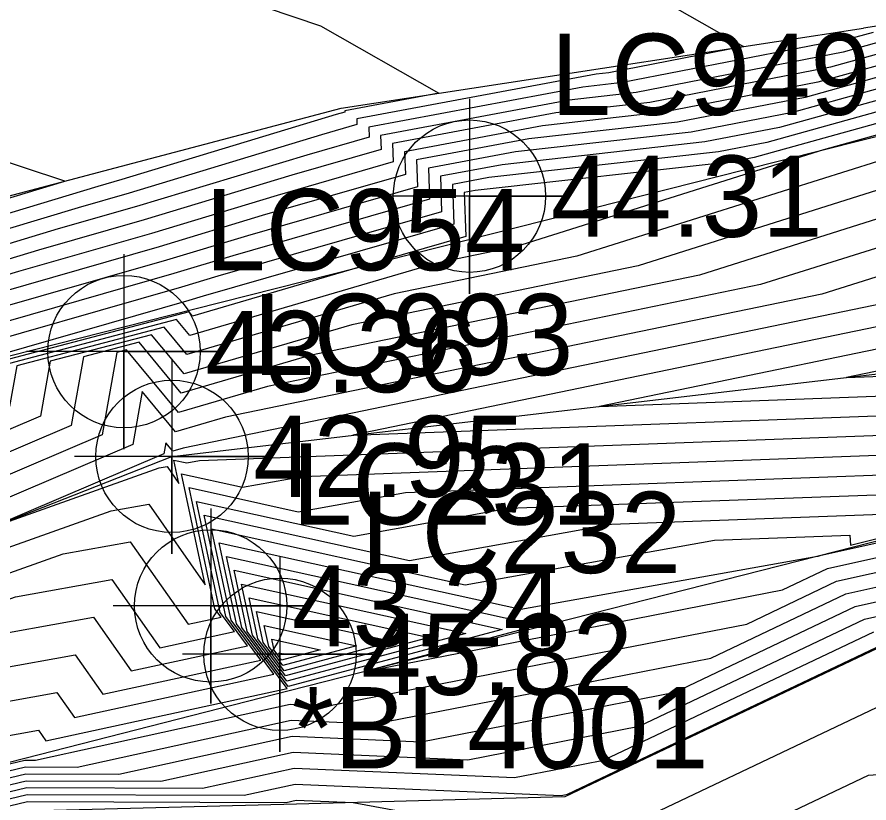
# Model space of a CAD drawing. Extents: x 2188792 to 2191981, y 386090 to 389710.
# Drawn here: x 2190212.42 to 2190238.64, y 387929.77 to 387953.95 of the extents above; entities that cross this region are included whole.
import ezdxf

# ---------------------------------------------------------------- set-up
doc = ezdxf.new("R2010")
doc.units = 0
for name, color, linetype in [('DTM Contours Major', 7, 'Continuous'), ('DTM Contours Minor', 7, 'Continuous'), ('Exist DTM Breakline Underwater', 7, 'Continuous'), ('Exist DTM Breakline Underwater Cogo Elevation', 7, 'Continuous'), ('Exist DTM Breakline Underwater Cogo Number', 7, 'Continuous'), ('Exist DTM Breakline Underwater Cogo Point CELL', 7, 'Continuous'), ('Exist DTM Regular Point Underwater CELL', 7, 'Continuous'), ('Exist DTM Regular Point Underwater Cogo Comment', 7, 'Continuous'), ('Exist DTM Regular Point Underwater Cogo Elevation', 7, 'Continuous'), ('Exist DTM Regular Point Underwater Cogo Number', 7, 'Continuous'), ('PH Exist DTM Breakline', 7, 'Continuous')]:
    doc.layers.add(name, color=color, linetype=linetype)

msp = doc.modelspace()

# ---------------------------------------------------------------- linework, layer by layer
at = {"layer": 'DTM Contours Major'}
for points in [[(2190238.761, 387953.476), (2190238.236, 387953.33), (2190231.049, 387951.931), (2190229.826, 387951.794), (2190223.241, 387950.56), (2190223.252, 387950.255), (2190221.331, 387949.704), (2190216.099, 387948.12), (2190213.685, 387947.428), (2190208.783, 387945.95), (2190204.376, 387944.62), (2190201.304, 387943.745), (2190197.863, 387942.764), (2190191.097, 387939.659), (2190187.751, 387938.056), (2190186.22, 387937.225), (2190179.234, 387934.025), (2190177.951, 387933.325)], [(2190241.141, 387952.366), (2190236.279, 387951.015), (2190233.163, 387950.409), (2190227.76, 387949.804), (2190225.079, 387949.301), (2190225.113, 387948.341), (2190219.055, 387946.601), (2190217.247, 387946.054), (2190210.637, 387944.16), (2190209.214, 387943.73), (2190207.934, 387943.344), (2190201.011, 387941.371), (2190193.254, 387939.16), (2190192.262, 387938.705), (2190191.772, 387938.47), (2190185.14, 387934.868), (2190184.293, 387934.48), (2190177.559, 387930.807)], [(2190243.465, 387950.942), (2190236.16, 387948.641), (2190229.647, 387946.589), (2190224.024, 387945.428), (2190217.646, 387943.561), (2190216.945, 387944.409), (2190212.415, 387943.221), (2190212.19, 387941.963), (2190203.611, 387938.301), (2190198.377, 387936.644), (2190193.887, 387935.221), (2190192.821, 387934.763), (2190189.103, 387932.693), (2190185.528, 387930.702), (2190172.055, 387924.838)], [(2190239.074, 387945.134), (2190217.532, 387940.686), (2190217.208, 387940.591), (2190216.993, 387940.852), (2190216.931, 387940.51), (2190211.569, 387938.221), (2190216.791, 387940.078), (2190217.034, 387940.122), (2190217.401, 387939.598), (2190217.247, 387940.318), (2190217.643, 387940.231), (2190218.033, 387940.301), (2190242.904, 387941.223)], [(2190174.772, 387918.95), (2190187.655, 387925.086), (2190191.189, 387926.924), (2190194.861, 387928.834), (2190195.881, 387929.317), (2190200.477, 387930.285), (2190209.419, 387933.465), (2190214.208, 387934.324), (2190215.059, 387933.111), (2190219.916, 387934.166), (2190219.005, 387935.394), (2190218.404, 387938.199), (2190226.213, 387936.479), (2190233.879, 387937.854), (2190238.048, 387938.009), (2190238.066, 387937.699), (2190244.835, 387939.381)], [(2190175.323, 387915.538), (2190181.724, 387918.921), (2190182.593, 387919.342), (2190188.861, 387922.648), (2190189.628, 387923.046), (2190195.733, 387926.265), (2190196.621, 387926.724), (2190203.158, 387928.251), (2190204.711, 387928.684), (2190206.464, 387929.173), (2190212.686, 387930.663), (2190215.555, 387930.653), (2190220.883, 387931.821), (2190224.858, 387931.651), (2190229.111, 387932.482), (2190232.668, 387933.178), (2190238.216, 387935.813), (2190241.557, 387936.557)], [(2190219.56, 387936.08), (2190225.106, 387934.858), (2190220.677, 387933.675), (2190219.831, 387934.816), (2190219.56, 387936.08)], [(2190174.341, 387884.909), (2190179.78, 387876.537), (2190184.682, 387879.952), (2190189.719, 387877.326), (2190192.093, 387885.619), (2190199.916, 387886.43), (2190200.828, 387887.573), (2190201.355, 387888.233), (2190200.535, 387890.18), (2190200.972, 387898.729), (2190211.107, 387898.557), (2190228.203, 387913.529), (2190222.305, 387928.372), (2190230.642, 387926.831), (2190238.626, 387930.623), (2190241.69, 387930.853)]]:
    msp.add_lwpolyline(points, dxfattribs=at)
at = {"layer": 'DTM Contours Minor'}
for points in [[(2190208.525, 387947.281), (2190213.89, 387948.9), (2190208.847, 387950.558), (2190207.29, 387949.272), (2190201.069, 387949.623), (2190198.133, 387949.956), (2190190.044, 387946.776), (2190181.258, 387951.986), (2190179.765, 387960.073)], [(2190227.6, 387957.129), (2190234.774, 387953.043), (2190230.626, 387952.236), (2190230.239, 387952.193), (2190222.873, 387950.812), (2190222.879, 387950.638), (2190221.786, 387950.324), (2190215.869, 387948.533), (2190214.294, 387948.082), (2190208.697, 387946.394), (2190203.664, 387944.875), (2190201.363, 387944.219), (2190198.785, 387943.484), (2190190.864, 387939.85), (2190186.947, 387937.973), (2190186.437, 387937.696), (2190178.222, 387933.934)], [(2190216.682, 387955.398), (2190221.76, 387953.676), (2190225.395, 387951.605), (2190222.506, 387951.063), (2190222.507, 387951.021), (2190222.242, 387950.945), (2190215.639, 387948.946), (2190214.904, 387948.736), (2190208.611, 387946.838), (2190202.953, 387945.131), (2190201.422, 387944.694), (2190199.706, 387944.205), (2190190.631, 387940.041), (2190187.233, 387938.413), (2190184.778, 387941.158), (2190178.644, 387939.932), (2190174.81, 387940.464)], [(2190239.713, 387953.032), (2190237.453, 387952.404), (2190231.894, 387951.323), (2190228.999, 387950.998), (2190223.976, 387950.056), (2190223.996, 387949.49), (2190220.421, 387948.463), (2190216.558, 387947.293), (2190212.465, 387946.121), (2190208.955, 387945.062), (2190205.799, 387944.11), (2190201.187, 387942.795), (2190196.019, 387941.322), (2190191.563, 387939.277), (2190189.359, 387938.222), (2190185.788, 387936.282), (2190181.257, 387934.207), (2190177.794, 387932.318)], [(2190239.237, 387953.254), (2190237.845, 387952.867), (2190231.472, 387951.627), (2190229.413, 387951.396), (2190223.608, 387950.308), (2190223.624, 387949.873), (2190220.876, 387949.083), (2190216.328, 387947.707), (2190213.075, 387946.775), (2190208.869, 387945.506), (2190205.087, 387944.365), (2190201.246, 387943.27), (2190196.941, 387942.043), (2190191.33, 387939.468), (2190188.555, 387938.139), (2190186.004, 387936.753), (2190180.245, 387934.116), (2190177.873, 387932.822)], [(2190240.189, 387952.81), (2190237.062, 387951.941), (2190232.317, 387951.018), (2190228.586, 387950.6), (2190224.344, 387949.805), (2190224.368, 387949.107), (2190219.965, 387947.842), (2190216.788, 387946.88), (2190211.856, 387945.467), (2190209.041, 387944.618), (2190206.51, 387943.855), (2190201.128, 387942.32), (2190195.097, 387940.601), (2190191.796, 387939.086), (2190190.164, 387938.304), (2190185.572, 387935.811), (2190182.269, 387934.298), (2190177.716, 387931.814)], [(2190240.665, 387952.588), (2190236.67, 387951.478), (2190232.74, 387950.714), (2190228.173, 387950.202), (2190224.711, 387949.553), (2190224.741, 387948.724), (2190219.51, 387947.221), (2190217.017, 387946.467), (2190211.246, 387944.813), (2190209.128, 387944.174), (2190207.222, 387943.599), (2190201.07, 387941.846), (2190194.175, 387939.88), (2190192.029, 387938.896), (2190190.968, 387938.387), (2190185.356, 387935.339), (2190183.281, 387934.389), (2190177.638, 387931.31)], [(2190241.616, 387952.144), (2190235.887, 387950.552), (2190233.585, 387950.105), (2190227.346, 387949.406), (2190225.447, 387949.05), (2190225.485, 387947.958), (2190218.6, 387945.98), (2190217.477, 387945.64), (2190210.027, 387943.506), (2190209.3, 387943.286), (2190208.645, 387943.089), (2190200.952, 387940.896), (2190194.479, 387939.051), (2190192.511, 387938.427), (2190192.475, 387938.412), (2190185.286, 387934.409), (2190178.375, 387930.561), (2190176.934, 387929.934)], [(2190242.092, 387951.922), (2190235.496, 387950.09), (2190234.008, 387949.8), (2190226.933, 387949.008), (2190225.814, 387948.798), (2190225.858, 387947.575), (2190218.144, 387945.36), (2190217.706, 387945.227), (2190209.418, 387942.852), (2190209.386, 387942.842), (2190209.357, 387942.834), (2190208.733, 387942.656), (2190200.532, 387940.058), (2190192.855, 387937.626), (2190192.561, 387937.5), (2190186.241, 387933.98), (2190180.163, 387930.596), (2190175.714, 387928.66)], [(2190243.044, 387951.478), (2190237.242, 387949.866), (2190234.984, 387949.155), (2190227.762, 387946.88), (2190225.322, 387946.376), (2190217.734, 387944.155), (2190217.33, 387944.644), (2190211.391, 387943.086), (2190211.242, 387942.254), (2190205.567, 387939.832), (2190199.096, 387937.782), (2190193.543, 387936.023), (2190192.735, 387935.675), (2190188.149, 387933.122), (2190183.739, 387930.667), (2190173.274, 387926.112)], [(2190242.568, 387951.7), (2190235.104, 387949.627), (2190234.431, 387949.496), (2190226.52, 387948.609), (2190226.182, 387948.546), (2190226.23, 387947.193), (2190222.987, 387946.261), (2190217.822, 387944.749), (2190217.715, 387944.878), (2190210.367, 387942.951), (2190210.294, 387942.545), (2190207.523, 387941.362), (2190199.814, 387938.92), (2190193.199, 387936.824), (2190192.648, 387936.588), (2190187.195, 387933.551), (2190181.951, 387930.632), (2190174.494, 387927.386)], [(2190243.847, 387950.177), (2190237.337, 387948.126), (2190231.533, 387946.298), (2190222.725, 387944.479), (2190217.559, 387942.967), (2190216.56, 387944.175), (2190213.439, 387943.356), (2190213.139, 387941.672), (2190201.654, 387936.771), (2190197.659, 387935.505), (2190194.231, 387934.419), (2190192.908, 387933.851), (2190190.057, 387932.264), (2190187.316, 387930.737), (2190170.835, 387923.564)], [(2190244.228, 387949.412), (2190238.513, 387947.612), (2190233.418, 387946.007), (2190221.427, 387943.531), (2190217.471, 387942.373), (2190216.176, 387943.941), (2190214.464, 387943.492), (2190214.087, 387941.382), (2190199.698, 387935.241), (2190196.941, 387934.367), (2190194.575, 387933.618), (2190192.995, 387932.939), (2190191.011, 387931.835), (2190189.104, 387930.773), (2190169.615, 387922.29)], [(2190239.69, 387947.098), (2190235.303, 387945.716), (2190220.129, 387942.582), (2190217.384, 387941.779), (2190215.791, 387943.706), (2190215.488, 387943.627), (2190215.035, 387941.091), (2190197.741, 387933.71), (2190196.222, 387933.229), (2190194.919, 387932.816), (2190193.081, 387932.027), (2190191.965, 387931.405), (2190190.892, 387930.808), (2190168.395, 387921.016)], [(2190240.867, 387946.584), (2190237.189, 387945.425), (2190218.831, 387941.634), (2190217.296, 387941.185), (2190216.273, 387942.423), (2190215.983, 387940.8), (2190195.785, 387932.18), (2190195.504, 387932.091), (2190195.263, 387932.015), (2190193.168, 387931.115), (2190192.919, 387930.976), (2190192.68, 387930.843), (2190167.175, 387919.742)], [(2190240.959, 387944.843), (2190222.749, 387941.082), (2190243.875, 387941.865)], [(2190242.845, 387944.552), (2190230.345, 387941.971), (2190244.846, 387942.508)], [(2190244.73, 387944.261), (2190237.94, 387942.859), (2190245.817, 387943.151)], [(2190167.739, 387918.52), (2190192.822, 387930.467), (2190193.059, 387930.59), (2190193.305, 387930.718), (2190195.37, 387931.698), (2190195.617, 387931.749), (2190215.316, 387938.755), (2190216.469, 387938.962), (2190218.21, 387936.481), (2190217.478, 387939.895), (2190219.357, 387939.481), (2190221.202, 387939.812), (2190241.932, 387940.58)], [(2190169.497, 387918.627), (2190191.531, 387929.122), (2190192.591, 387929.674), (2190193.694, 387930.247), (2190195.498, 387931.103), (2190196.832, 387931.383), (2190213.842, 387937.433), (2190215.903, 387937.803), (2190217.685, 387935.264), (2190218.699, 387935.484), (2190218.509, 387935.741), (2190217.71, 387939.471), (2190221.071, 387938.73), (2190224.371, 387939.322), (2190240.961, 387939.937)], [(2190171.256, 387918.735), (2190190.239, 387927.777), (2190192.124, 387928.757), (2190194.083, 387929.776), (2190195.625, 387930.507), (2190198.047, 387931.017), (2190212.368, 387936.11), (2190215.338, 387936.643), (2190216.809, 387934.546), (2190219.105, 387935.045), (2190218.674, 387935.625), (2190217.941, 387939.047), (2190222.785, 387937.98), (2190227.54, 387938.833), (2190239.99, 387939.294)], [(2190176.531, 387919.057), (2190186.364, 387923.741), (2190190.722, 387926.007), (2190195.25, 387928.362), (2190196.009, 387928.722), (2190201.693, 387929.919), (2190207.945, 387932.143), (2190213.642, 387933.165), (2190214.184, 387932.394), (2190220.321, 387933.727), (2190219.17, 387935.278), (2190218.635, 387937.775), (2190227.927, 387935.728), (2190237.048, 387937.365), (2190237.077, 387937.366), (2190237.077, 387937.364), (2190237.167, 387937.387), (2190244.751, 387939.075)], [(2190173.014, 387918.842), (2190188.947, 387926.431), (2190191.657, 387927.841), (2190194.472, 387929.305), (2190195.753, 387929.912), (2190199.262, 387930.651), (2190210.894, 387934.788), (2190214.773, 387935.484), (2190215.934, 387933.829), (2190219.51, 387934.606), (2190218.839, 387935.509), (2190218.172, 387938.623), (2190224.499, 387937.229), (2190230.71, 387938.344), (2190239.019, 387938.652)], [(2190178.289, 387919.165), (2190185.072, 387922.396), (2190190.254, 387925.091), (2190195.639, 387927.891), (2190196.136, 387928.127), (2190202.908, 387929.553), (2190206.471, 387930.82), (2190213.077, 387932.005), (2190213.308, 387931.676), (2190220.727, 387933.288), (2190219.335, 387935.163), (2190218.866, 387937.352), (2190228.468, 387935.236), (2190223.124, 387933.808), (2190228.954, 387934.948), (2190235.975, 387936.321), (2190237.355, 387936.977), (2190243.953, 387938.445)], [(2190173.758, 387916.019), (2190180.047, 387919.272), (2190183.78, 387921.05), (2190189.787, 387924.174), (2190196.028, 387927.42), (2190196.264, 387927.532), (2190204.123, 387929.187), (2190204.997, 387929.497), (2190209.081, 387930.23), (2190212.659, 387931.087), (2190212.983, 387931.086), (2190220.82, 387932.805), (2190221.99, 387932.754), (2190229.006, 387934.126), (2190234.873, 387935.273), (2190237.642, 387936.589), (2190243.154, 387937.816)], [(2190174.734, 387915.723), (2190181.806, 387919.38), (2190182.488, 387919.705), (2190189.319, 387923.258), (2190192.136, 387924.723), (2190196.323, 387926.931), (2190196.401, 387926.971), (2190203.97, 387928.739), (2190204.595, 387928.913), (2190205.302, 387929.11), (2190212.673, 387930.875), (2190214.269, 387930.87), (2190220.852, 387932.313), (2190223.424, 387932.203), (2190229.059, 387933.304), (2190233.77, 387934.226), (2190237.929, 387936.201), (2190242.356, 387937.186)], [(2190219.098, 387936.928), (2190227.348, 387935.11), (2190220.76, 387933.35), (2190219.501, 387935.047), (2190219.098, 387936.928)], [(2190219.329, 387936.504), (2190226.227, 387934.984), (2190220.719, 387933.513), (2190219.666, 387934.932), (2190219.329, 387936.504)], [(2190175.67, 387915.423), (2190181.112, 387918.299), (2190183.101, 387919.263), (2190188.402, 387922.059), (2190189.991, 387922.882), (2190195.144, 387925.599), (2190196.84, 387926.478), (2190202.346, 387927.764), (2190204.826, 387928.455), (2190207.627, 387929.236), (2190212.7, 387930.451), (2190216.841, 387930.436), (2190220.915, 387931.33), (2190226.292, 387931.099), (2190229.164, 387931.66), (2190231.565, 387932.13), (2190238.503, 387935.425), (2190240.759, 387935.927)], [(2190219.792, 387935.656), (2190223.985, 387934.732), (2190220.636, 387933.838), (2190219.996, 387934.7), (2190219.792, 387935.656)], [(2190220.023, 387935.232), (2190222.864, 387934.606), (2190220.595, 387934), (2190220.162, 387934.585), (2190220.023, 387935.232)], [(2190176.017, 387915.308), (2190180.5, 387917.677), (2190183.609, 387919.184), (2190187.944, 387921.47), (2190190.353, 387922.718), (2190194.554, 387924.933), (2190197.06, 387926.231), (2190201.535, 387927.276), (2190204.941, 387928.226), (2190208.789, 387929.299), (2190212.714, 387930.239), (2190218.127, 387930.22), (2190220.946, 387930.838), (2190227.727, 387930.547), (2190229.217, 387930.839), (2190230.462, 387931.082), (2190238.79, 387935.037)], [(2190220.254, 387934.809), (2190221.743, 387934.481), (2190220.554, 387934.163), (2190220.327, 387934.469), (2190220.254, 387934.809)], [(2190176.364, 387915.193), (2190179.888, 387917.055), (2190184.117, 387919.105), (2190187.486, 387920.881), (2190190.715, 387922.554), (2190193.964, 387924.267), (2190197.28, 387925.985), (2190200.723, 387926.789), (2190205.056, 387927.997), (2190209.951, 387929.362), (2190212.727, 387930.027), (2190219.412, 387930.003), (2190220.977, 387930.346), (2190229.161, 387929.995), (2190229.269, 387930.017), (2190229.36, 387930.034), (2190239.077, 387934.649)], [(2190220.486, 387934.385), (2190220.622, 387934.355), (2190220.513, 387934.325), (2190220.492, 387934.354), (2190220.486, 387934.385)], [(2190176.711, 387915.078), (2190179.276, 387916.433), (2190184.625, 387919.025), (2190187.028, 387920.292), (2190191.077, 387922.39), (2190193.374, 387923.601), (2190197.5, 387925.738), (2190199.911, 387926.301), (2190205.171, 387927.768), (2190211.113, 387929.425), (2190212.741, 387929.815), (2190220.698, 387929.787), (2190221.009, 387929.855), (2190222.766, 387929.779), (2190229.93, 387928.455), (2190238.872, 387932.703)]]:
    msp.add_lwpolyline(points, dxfattribs=at)
at = {"layer": 'Exist DTM Breakline Underwater'}
msp.add_lwpolyline([(2190165.897, 387918.407), (2190195.341, 387931.833), (2190217.185, 387940.432), (2190258.084, 387945.215), (2190309.218, 387932.714), (2190343.089, 387929.481), (2190375.21, 387918.126)], dxfattribs=at)
at = {"layer": 'Exist DTM Breakline Underwater Cogo Point CELL'}
msp.add_lwpolyline([(2190217.185, 387943.432), (2190217.185, 387937.432), (2190217.185, 387940.432), (2190220.185, 387940.432), (2190214.185, 387940.432)], dxfattribs=at)
msp.add_circle((2190217.185, 387940.432), 2.344, dxfattribs=at)
at = {"layer": 'Exist DTM Regular Point Underwater CELL'}
for points in [[(2190226.341, 387951.437), (2190226.341, 387945.437), (2190226.341, 387948.437), (2190229.341, 387948.437), (2190223.341, 387948.437)], [(2190215.708, 387946.656), (2190215.708, 387940.656), (2190215.708, 387943.656), (2190218.708, 387943.656), (2190212.708, 387943.656)], [(2190218.378, 387938.832), (2190218.378, 387932.832), (2190218.378, 387935.832), (2190221.378, 387935.832), (2190215.378, 387935.832)], [(2190220.509, 387937.342), (2190220.509, 387931.342), (2190220.509, 387934.342), (2190223.509, 387934.342), (2190217.509, 387934.342)]]:
    msp.add_lwpolyline(points, dxfattribs=at)
for centre in [(2190226.341, 387948.437), (2190215.708, 387943.656), (2190218.378, 387935.832), (2190220.509, 387934.342)]:
    msp.add_circle(centre, 2.344, dxfattribs=at)
at = {"layer": 'PH Exist DTM Breakline'}
for points in [[(2190257.096, 387956.777), (2190250.145, 387955.381), (2190238.473, 387953.61)], [(2190109.829, 387900.589), (2190117.728, 387904.556), (2190125.627, 387908.523), (2190133.526, 387912.49), (2190141.824, 387916.341), (2190150.122, 387920.192), (2190161.927, 387925.89), (2190169.542, 387929.904), (2190178.043, 387933.918), (2190186.545, 387937.932), (2190190.139, 387940.444), (2190201.538, 387945.638), (2190208.488, 387947.473), (2190215.438, 387949.309), (2190222.388, 387951.144), (2190230.431, 387952.377), (2190238.473, 387953.61)], [(2190140.155, 387912.651), (2190146.114, 387916.254), (2190154.091, 387919.685), (2190162.069, 387923.115), (2190170.047, 387926.546), (2190177.519, 387930.544), (2190184.99, 387934.543), (2190192.462, 387938.541), (2190200.926, 387940.681), (2190209.39, 387942.822), (2190217.853, 387944.963), (2190226.317, 387947.103), (2190234.78, 387949.244), (2190243.244, 387951.384)], [(2190245.208, 387939.435), (2190237.07, 387937.362), (2190228.932, 387935.288), (2190220.794, 387933.215), (2190212.656, 387931.141), (2190204.518, 387929.068), (2190196.38, 387926.994), (2190189.289, 387923.199), (2190182.199, 387919.404), (2190175.109, 387915.609), (2190167.285, 387912.244), (2190159.46, 387908.88), (2190151.636, 387905.515), (2190141, 387899.082), (2190133.702, 387893.484)], [(2190301.394, 387927.26), (2190292.177, 387929.22), (2190282.959, 387931.179), (2190276.211, 387932.556), (2190269.463, 387933.933), (2190258.068, 387935.251), (2190247.423, 387935.199), (2190239.099, 387934.619), (2190229.273, 387929.952), (2190221.017, 387929.733), (2190212.76, 387929.514), (2190205.387, 387927.338), (2190198.014, 387925.162), (2190191.951, 387921.995), (2190185.888, 387918.828), (2190177.639, 387914.771), (2190169.39, 387910.713), (2190163.13, 387908.28), (2190156.87, 387905.846), (2190150.61, 387903.413), (2190143.688, 387898.862), (2190136.766, 387894.311)]]:
    msp.add_lwpolyline(points, dxfattribs=at)

# ---------------------------------------------------------------- texts
at = {"layer": 'Exist DTM Breakline Underwater Cogo Elevation'}
msp.add_text('42.95', height=2.5, dxfattribs=at).set_placement((2190219.685, 387939.182))
at = {"layer": 'Exist DTM Breakline Underwater Cogo Number'}
msp.add_text('LC993', height=2.5, dxfattribs=at).set_placement((2190219.685, 387942.932))
at = {"layer": 'Exist DTM Regular Point Underwater Cogo Comment'}
msp.add_text('*BL4001', height=2.5, dxfattribs=at).set_placement((2190220.878, 387930.832))
at = {"layer": 'Exist DTM Regular Point Underwater Cogo Elevation'}
for s, p in [('44.31', (2190228.841, 387947.187)), ('43.36', (2190218.208, 387942.406)), ('43.24', (2190220.878, 387934.582)), ('45.82', (2190223.009, 387933.092))]:
    msp.add_text(s, height=2.5, dxfattribs=at).set_placement(p)
at = {"layer": 'Exist DTM Regular Point Underwater Cogo Number'}
for s, p in [('LC949', (2190228.841, 387950.937)), ('LC954', (2190218.208, 387946.156)), ('LC231', (2190220.878, 387938.332)), ('LC232', (2190223.009, 387936.842))]:
    msp.add_text(s, height=2.5, dxfattribs=at).set_placement(p)

doc.saveas('drawing.dxf')
